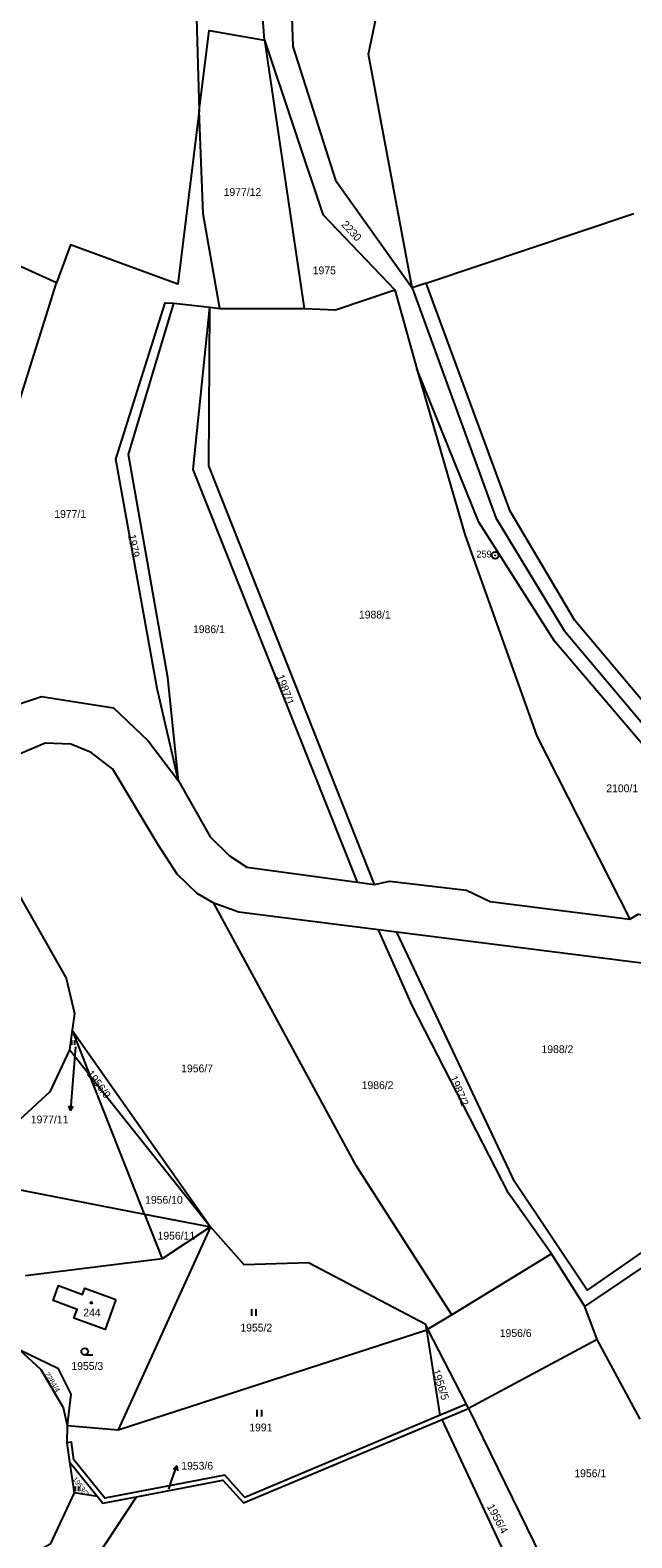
# Model space of a CAD drawing. Extents: x -725728 to -720881, y -1068679 to -1063504.
# Drawn here: x -722411.6 to -722280, y -1066626.7 to -1066297.3 of the extents above; entities that cross this region are included whole.
import ezdxf

# ---------------------------------------------------------------- set-up
doc = ezdxf.new("R2010")
doc.units = 0
for name, color, linetype in [('Hranice parcel', 7, 'Continuous'), ('Parcelní čísla', 7, 'Continuous'), ('Pop  PČ popisy', 7, 'Continuous'), ('Značky bodu BP', 7, 'Continuous'), ('Značky budov', 7, 'Continuous'), ('Značky kultur', 7, 'Continuous')]:
    doc.layers.add(name, color=color, linetype=linetype)

msp = doc.modelspace()

# ---------------------------------------------------------------- linework, layer by layer
at = {"layer": 'Hranice parcel'}
for p, q in [((-722360.39, -1066299.45), (-722351.71, -1066358.08)), ((-722405.85, -1066352.47), (-722442.14, -1066336.29)), ((-722325, -1066352.55), (-722279.58, -1066337.37)), ((-722414.99, -1066381.56), (-722405.85, -1066352.47)), ((-722325, -1066352.55), (-722328.1, -1066353.59)), ((-722380.22, -1066356.96), (-722372.35, -1066357.83)), ((-722331.84, -1066354.05), (-722327.06, -1066371.32)), ((-722372.35, -1066357.83), (-722370.11, -1066358.08)), ((-722370.11, -1066358.08), (-722351.71, -1066358.08)), ((-722340.06, -1066483.49), (-722336.3, -1066484)), ((-722331.4, -1066494.36), (-722335.44, -1066493.85)), ((-722275.02, -1066501.51), (-722331.4, -1066494.36)), ((-722402.45, -1066515.82), (-722403.04, -1066520.09)), ((-722402.45, -1066515.82), (-722398.54, -1066525.72)), ((-722402.45, -1066515.82), (-722372.16, -1066558.77)), ((-722398.54, -1066525.72), (-722403.04, -1066520.09)), ((-722398.54, -1066525.72), (-722372.16, -1066558.77)), ((-722386.61, -1066555.97), (-722398.54, -1066525.72)), ((-722490.4, -1066535.88), (-722386.61, -1066555.97)), ((-722290.32, -1066576.17), (-722248.53, -1066547.99)), ((-722386.61, -1066555.97), (-722372.16, -1066558.77)), ((-722386.61, -1066555.97), (-722382.75, -1066565.75)), ((-722372.16, -1066558.77), (-722392.37, -1066603.11)), ((-722372.16, -1066558.77), (-722382.75, -1066565.75)), ((-722297.57, -1066564.7), (-722319.43, -1066577.98)), ((-722290.32, -1066576.17), (-722297.57, -1066564.7)), ((-722382.75, -1066565.75), (-722412.64, -1066569.48)), ((-722287.63, -1066583.42), (-722290.32, -1066576.17)), ((-722324.89, -1066581.29), (-722325.11, -1066580.14)), ((-722324.61, -1066581.12), (-722325.11, -1066580.14)), ((-722319.43, -1066577.98), (-722324.61, -1066581.12)), ((-722316.2, -1066597.54), (-722324.61, -1066581.12)), ((-722392.37, -1066603.11), (-722324.89, -1066581.29)), ((-722321.93, -1066599.94), (-722324.89, -1066581.29)), ((-722287.63, -1066583.42), (-722315.76, -1066598.44)), ((-722278.19, -1066600.79), (-722287.63, -1066583.42)), ((-722316.2, -1066597.54), (-722321.93, -1066599.94)), ((-722315.76, -1066598.44), (-722316.2, -1066597.54)), ((-722321.53, -1066600.86), (-722315.76, -1066598.44)), ((-722302.32, -1066641.88), (-722321.53, -1066600.86)), ((-722315.76, -1066598.44), (-722295.58, -1066639.59)), ((-722403.53, -1066602.19), (-722403.58, -1066605.95)), ((-722403.53, -1066602.19), (-722392.37, -1066603.11)), ((-722403.58, -1066605.95), (-722403.04, -1066610.09)), ((-722403.04, -1066610.09), (-722396.9, -1066617.71)), ((-722403.04, -1066610.09), (-722401.98, -1066616.86)), ((-722396.9, -1066617.71), (-722401.98, -1066616.86))]:
    msp.add_line(p, q, dxfattribs=at)
for points in [[(-722328.1, -1066353.59), (-722337.63, -1066302.52), (-722327.98, -1066256.41), (-722320.39, -1066238.93), (-722295.1, -1066210.75), (-722291.09, -1066201.15), (-722292.06, -1066183.03)], [(-722360.39, -1066299.45), (-722365.44, -1066231.99), (-722361.3, -1066211.21)], [(-722356.78, -1066224.74), (-722354.14, -1066300.89), (-722344.87, -1066330.05), (-722328.1, -1066353.59)], [(-722397.49, -1066242.41), (-722376.51, -1066251.39), (-722374.63, -1066314.93)], [(-722374.63, -1066314.93), (-722372.45, -1066297.37), (-722360.39, -1066299.45)], [(-722360.39, -1066299.45), (-722347.64, -1066337.58), (-722331.84, -1066354.05)], [(-722374.63, -1066314.93), (-722379.33, -1066352.77), (-722402.83, -1066344.17), (-722405.85, -1066352.47)], [(-722370.11, -1066358.08), (-722373.75, -1066337.42), (-722374.63, -1066314.93)], [(-722328.1, -1066353.59), (-722309.79, -1066403.88), (-722294.79, -1066428.46), (-722273.01, -1066454.36), (-722245.66, -1066479.61), (-722215.91, -1066496.61), (-722206.37, -1066505.53)], [(-722191.9, -1066464.38), (-722205.02, -1066485.03), (-722211.63, -1066495.43), (-722242.53, -1066476.29), (-722270.43, -1066452.53), (-722292.48, -1066426.31), (-722306.67, -1066402.36), (-722325, -1066352.55)], [(-722379.21, -1066461.34), (-722383.85, -1066441.16), (-722392.86, -1066391.06), (-722382.1, -1066356.87), (-722380.22, -1066356.96)], [(-722379.21, -1066461.34), (-722381.54, -1066438.73), (-722390.08, -1066390.04), (-722380.22, -1066356.96)], [(-722351.71, -1066358.08), (-722344.87, -1066358.4), (-722331.84, -1066354.05)], [(-722340.06, -1066483.49), (-722375.97, -1066393.27), (-722372.35, -1066357.83)], [(-722336.3, -1066484), (-722372.55, -1066392.47), (-722372.35, -1066357.83)], [(-722327.06, -1066371.32), (-722316.57, -1066407.47), (-722300.77, -1066451.58), (-722280.45, -1066491.52)], [(-722217.19, -1066499.9), (-722245.66, -1066484.11), (-722272.88, -1066459), (-722296.92, -1066430.83), (-722313.51, -1066404.8), (-722327.06, -1066371.32)], [(-722427.29, -1066452.19), (-722418.01, -1066445.87), (-722409.11, -1066442.91), (-722393.39, -1066445.36), (-722385.78, -1066452.58), (-722379.21, -1066461.34)], [(-722371.47, -1066488.08), (-722375.09, -1066485.97), (-722379.47, -1066481.72), (-722383.59, -1066475.27), (-722393.52, -1066458.77), (-722398.29, -1066455.15), (-722402.72, -1066453.28), (-722408.31, -1066453.09), (-722413.81, -1066455.39), (-722417.57, -1066459.7), (-722420.51, -1066465.75), (-722416.97, -1066481.2), (-722403.76, -1066504.41), (-722401.94, -1066512.16), (-722402.45, -1066515.82)], [(-722379.21, -1066461.34), (-722372.25, -1066473.59), (-722368, -1066477.72), (-722364.26, -1066480.17), (-722340.06, -1066483.49)], [(-722336.3, -1066484), (-722333.06, -1066483.26), (-722316.18, -1066485.2), (-722311.02, -1066487.65), (-722280.45, -1066491.52)], [(-722335.44, -1066493.85), (-722357.94, -1066491), (-722365.96, -1066490.04), (-722371.47, -1066488.08)], [(-722319.43, -1066577.98), (-722340.26, -1066545.53), (-722371.47, -1066488.08)], [(-722280.45, -1066491.52), (-722278.67, -1066490.48), (-722217.19, -1066499.9)], [(-722297.57, -1066564.7), (-722307.01, -1066551.38), (-722328.08, -1066510.4), (-722335.44, -1066493.85)], [(-722250.36, -1066545.32), (-722289.82, -1066572.63), (-722305.66, -1066548.85), (-722331.4, -1066494.36)], [(-722403.04, -1066520.09), (-722407.31, -1066529.3), (-722414.99, -1066536.37), (-722424.74, -1066538.75), (-722433.7, -1066538.5)], [(-722325.11, -1066580.14), (-722350.72, -1066566.61), (-722364.85, -1066567.05), (-722372.16, -1066558.77)], [(-722392.86, -1066574.67), (-722395.24, -1066581.19), (-722402.05, -1066578.7), (-722401.36, -1066576.8), (-722406.6, -1066574.89), (-722405.41, -1066571.62), (-722400.17, -1066573.53), (-722399.68, -1066572.18), (-722392.86, -1066574.67)], [(-722414.04, -1066585.59), (-722405.58, -1066589.65), (-722402.72, -1066595.3), (-722403.53, -1066602.19)], [(-722414.04, -1066585.59), (-722409.27, -1066589.97), (-722404.43, -1066598.22), (-722403.53, -1066602.19)], [(-722321.93, -1066599.94), (-722364.68, -1066617.89), (-722369.08, -1066613.02), (-722395.32, -1066618.08), (-722402.08, -1066609.68), (-722402.59, -1066605.82), (-722403.58, -1066605.95)], [(-722388.36, -1066617.76), (-722369.45, -1066614.11), (-722364.95, -1066619.09), (-722321.53, -1066600.86)], [(-722401.98, -1066616.86), (-722407.23, -1066628.11), (-722417.49, -1066633.85), (-722426.21, -1066634.27), (-722433.39, -1066632.11), (-722450.22, -1066623.28), (-722463.67, -1066621.54)], [(-722369.74, -1066659.53), (-722410.53, -1066651.31), (-722388.36, -1066617.76)], [(-722396.9, -1066617.71), (-722395.72, -1066619.18), (-722388.36, -1066617.76)]]:
    msp.add_lwpolyline(points, dxfattribs=at)
at = {"layer": 'Pop  PČ popisy'}
for p, q in [((-722401.73, -1066519.46), (-722402.56, -1066530.35)), ((-722402.56, -1066530.35), (-722402.77, -1066533.34)), ((-722402.77, -1066533.34), (-722403.2, -1066532.31)), ((-722402.77, -1066533.34), (-722402.2, -1066532.38)), ((-722381.31, -1066616.06), (-722380.54, -1066613.82)), ((-722380.54, -1066613.82), (-722379.56, -1066610.98)), ((-722379.56, -1066610.98), (-722380.36, -1066611.77)), ((-722379.56, -1066610.98), (-722379.42, -1066612.09))]:
    msp.add_line(p, q, dxfattribs=at)
at = {"layer": 'Značky bodu BP'}
for radius in [0.75, 0.03]:
    msp.add_circle((-722309.92, -1066412.03), radius, dxfattribs=at)
at = {"layer": 'Značky budov'}
msp.add_circle((-722398.24, -1066575.37), 0.175, dxfattribs=at)
at = {"layer": 'Značky kultur'}
for p, q in [((-722402.52, -1066518.99), (-722402.52, -1066517.99)), ((-722401.85, -1066518.99), (-722401.85, -1066517.99)), ((-722363.17, -1066578.25), (-722363.17, -1066576.75)), ((-722362.17, -1066578.25), (-722362.17, -1066576.75)), ((-722399.67, -1066586.77), (-722397.92, -1066586.77)), ((-722361.95, -1066600.24), (-722361.95, -1066598.74)), ((-722360.95, -1066600.24), (-722360.95, -1066598.74)), ((-722401.68, -1066616.53), (-722401.68, -1066615.53)), ((-722401.01, -1066616.53), (-722401.01, -1066615.53))]:
    msp.add_line(p, q, dxfattribs=at)
msp.add_circle((-722399.67, -1066586.02), 0.75, dxfattribs=at)

# ---------------------------------------------------------------- texts
at = {"layer": 'Parcelní čísla'}
for s, p in [('1977/12', (-722369.3, -1066333.52)), ('1975', (-722349.81, -1066350.63)), ('1977/1', (-722406.35, -1066403.86)), ('1988/1', (-722339.71, -1066425.85)), ('1986/1', (-722376.01, -1066429.04)), ('2100/1', (-722285.61, -1066463.81)), ('1988/2', (-722299.78, -1066520.81)), ('1956/7', (-722378.59, -1066525.01)), ('1986/2', (-722339.11, -1066528.67)), ('1977/11', (-722411.47, -1066536.17)), ('1956/10', (-722386.47, -1066553.72)), ('1956/11', (-722383.76, -1066561.56)), ('244', (-722400.01, -1066578.36)), ('1955/2', (-722365.64, -1066581.65)), ('1956/6', (-722308.91, -1066582.84)), ('1955/3', (-722402.6, -1066590.02)), ('1991', (-722363.69, -1066603.46)), ('1953/6', (-722378.57, -1066611.83)), ('1956/1', (-722292.59, -1066613.48))]:
    msp.add_text(s, height=1.7, dxfattribs=at).set_placement(p)
for s, height, rotation, p in [('2230', 1.7, 313, (-722343.67, -1066339.88)), ('1979', 1.7, 281, (-722390.24, -1066407.63)), ('1987/1', 1.7, 290, (-722357.8, -1066438.44)), ('1956/9', 1.7, 307, (-722399.39, -1066525.34)), ('1987/2', 1.7, 293, (-722319.92, -1066526.16)), ('2284/4', 1.14, 302, (-722408.5, -1066590.97)), ('1956/5', 1.7, 288, (-722323.72, -1066590.18)), ('1953/7', 1.14, 306, (-722402.45, -1066613.9)), ('1956/4', 1.7, 298, (-722311.77, -1066619.87))]:
    msp.add_text(s, height=height, rotation=rotation, dxfattribs=at).set_placement(p)
at = {"layer": 'Značky bodu BP'}
msp.add_text('259', height=1.5, dxfattribs=at).set_placement((-722314.02, -1066412.53))

doc.saveas('drawing.dxf')
